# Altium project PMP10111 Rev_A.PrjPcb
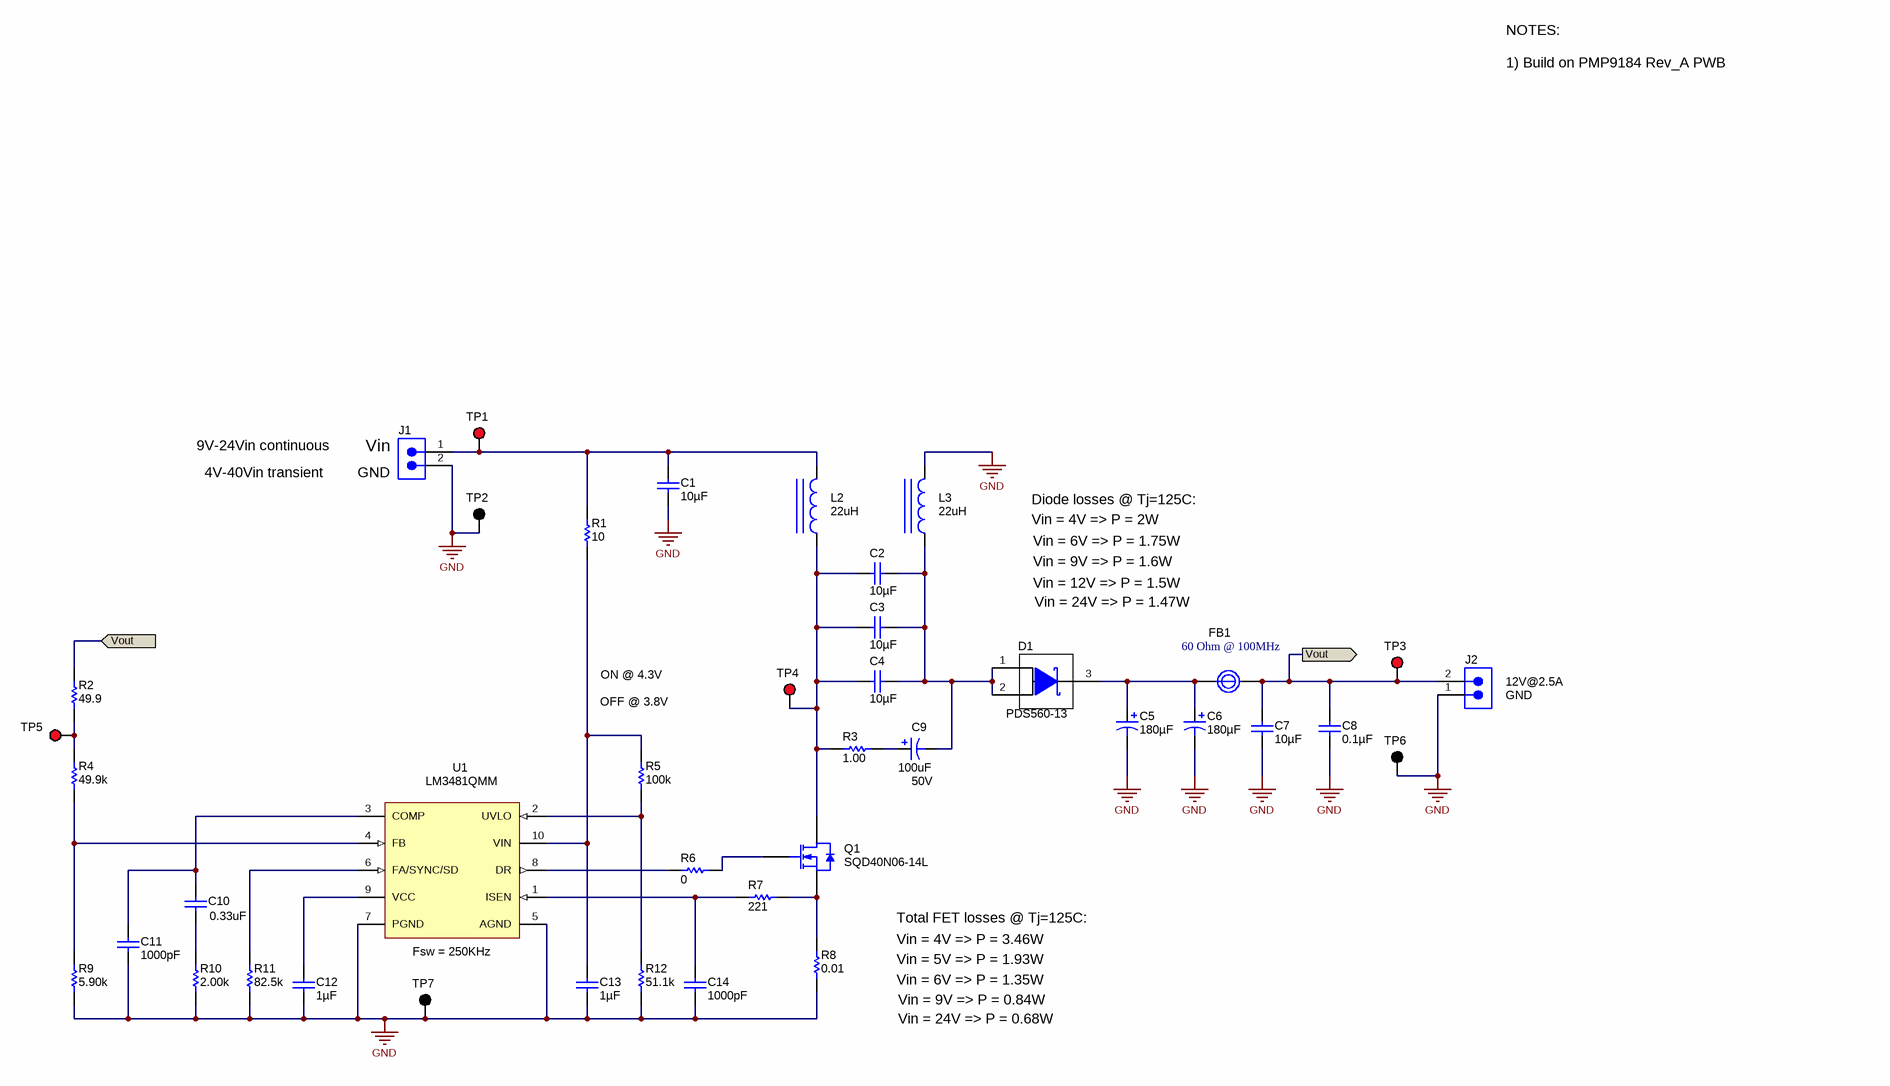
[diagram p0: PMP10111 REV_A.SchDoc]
CopyrightYear: 2014; PCB_Layout: R. Scibilia; PCB_Rev: A; PRJ_Customer: Public Release; PRJ_Engineer: R. Scibilia; PRJ_Number: PMP10111; PRJ_Title: LM3481 SEPIC converter; SCH_Rev: A; TechSupport: http://www.ti.com/support
1 sheet, 41 parts. Net scope: flat (ports and power ports of the same name join across sheets).

## Sheet PMP10111 REV_A.SchDoc: LM3481 SEPIC converter
size 431 x 279 mm; Date: Not shown in title block; ApprovedBy: Not shown in title block; CheckedBy: Not shown in title block; Author: Not shown in title block; CompanyName: Not shown in title block; DrawnBy: R. Scibilia; Engineer: Not shown in title block; Organization: Not shown in title block; Address1: Not shown in title block; Address2: Not shown in title block; Address3: Not shown in title block; Address4: Not shown in title block; DocumentNumber: 1; Revision: Use project parameter SCH_Rev; SheetNumber: 1; SheetTotal: 1; PageSetup: Record=PageOptions|CenterHorizontal=True|CenterVertical=True|PrintScale=1.00|XCorrection=1.00|YCorrection=1.00|PrintKind=0|BorderSize=5000000|LeftOffset=0|BottomOffset=0|Orientation=2|PaperLength=1000|PaperWidth=1000|Scale=100|PaperSource=15|PrintQuality=600|MediaType=1|DitherType=10|PaperKind=Letter|PrintScaleMode=1

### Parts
C1  ValueDisplayed: 10µF  [1210]  (hidden comment: GRM32ER71H106KA12L)
C2  ValueDisplayed: 10µF  [1210]  (hidden comment: GRM32ER71H106KA12L)
C3  ValueDisplayed: 10µF  [1210]  (hidden comment: GRM32ER71H106KA12L)
C4  ValueDisplayed: 10µF  [1210]  (hidden comment: GRM32ER71H106KA12L)
C5  ValueDisplayed: 180µF  [SM_RADIAL_10AMM]  (hidden comment: 25SVPF180M)
C6  ValueDisplayed: 180µF  [SM_RADIAL_10AMM]  (hidden comment: 25SVPF180M)
C7  ValueDisplayed: 10µF  [1210L]  (hidden comment: C3225X7R1E106M250AC)
C8  ValueDisplayed: 0.1µF  [0603L]  (hidden comment: C1608X7R1H104K)
C9  value 100uF  Value2: 50V  [SM_RADIAL_F]  (hidden comment: EEE-FK1H101P)
C10  value 0.33uF  [0603]  (hidden comment: GRM188R71C334KA01D)
C11  ValueDisplayed: 1000pF  [0603L]  (hidden comment: C1608X7R1H102K)
C12  ValueDisplayed: 1µF  [0603L]  (hidden comment: C1608X7R1E105K)
C13  ValueDisplayed: 1µF  [0603L]  (hidden comment: C1608X7R1E105K)
C14  ValueDisplayed: 1000pF  [0603L]  (hidden comment: C1608X7R1H102K)
D1  PDS560-13  [PowerDI5]
FB1  value 60 Ohm @ 100MHz  [BEAD-BLM41]  (hidden comment: BLM41PG600SH1)
J1  ED555/2DS  [TERM_BLK_ED555-2DS]  (value not drawn)
J2  ED555/2DS  [TERM_BLK_ED555-2DS]  (value not drawn)
L2  value 22uH  [IND_WE-HCI_2212]  (hidden comment: IHLP6767GZER220M5A)
L3  value 22uH  [WE-HCA2]  (hidden comment: IHLP4040DZER220M5A)
Q1  SQD40N06-14L  [DPAK]
R1  value 10  [0603L]  (hidden comment: CRCW060310R0JNEA)
R2  value 49.9  [0603L]  (hidden comment: CRCW060349R9FKEA)
R3  value 1.00  [1206L]  (hidden comment: CRCW12061R00FKEA)
R4  value 49.9k  [0603L]  (hidden comment: CRCW060349K9FKEA)
R5  value 100k  [0603L]  (hidden comment: CRCW0603100KFKEA)
R6  value 0  [0603L]  (hidden comment: CRCW06030000Z0EA)
R7  value 221  [0603L]  (hidden comment: CRCW0603221RFKEA)
R8  ValueDisplayed: 0.01  [2512]  (hidden comment: ERJ-M1WSF10MU)
R9  ValueDisplayed: 5.90k  [0603]  (hidden comment: CRCW06035K90FKEA)
R10  value 2.00k  [0603L]  (hidden comment: CRCW06032K00FKEA)
R11  ValueDisplayed: 82.5k  [0603]  (hidden comment: CRCW060382K5FKEA)
R12  ValueDisplayed: 51.1k  [0603]  (hidden comment: CRCW060351K1FKEA)
TP1  5000  [Keystone5000]  (value not drawn)
TP2  5001  [Keystone5001]  (value not drawn)
TP3  5000  [Keystone5000]  (value not drawn)
TP4  5000  [Keystone5000]  (value not drawn)
TP5  5000  [Keystone5000]  (value not drawn)
TP6  5001  [Keystone5001]  (value not drawn)
TP7  5001  [Keystone5001]  (value not drawn)
U1  value LM3481QMM  [MUB10A_L]  (hidden comment: LM3481MM)

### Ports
Vout

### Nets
GND: C1.2 C5.2(-) C6.2(-) C7.1 C8.2 C11.2 C12.2 C13.2 C14.2 J1.2 J2.1 L3.2 R8.1 R9.1 R10.1 R11.1 R12.1 TP2.1 TP6.1 TP7.1 U1.5(AGND) U1.7(PGND)
Vout: C7.2 C8.1 FB1.2 J2.2 R2.2 TP3.1 ; port Vout
NetC1_1: C1.1 J1.1 L2.2 R1.2 TP1.1
NetC2_1: C2.1 C3.1 C4.1 C9.2(-) D1.1(A) D1.2(A) L3.1
NetC2_2: C2.2 C3.2 C4.2 L2.1 Q1.4(D) R3.1 TP4.1
NetC5_1: C5.1(+) C6.1(+) D1.3(K) FB1.1
NetC9_1: C9.1(+) R3.2
NetC10_1: C10.1 C11.1 U1.3(COMP)
NetC10_2: C10.2 R10.2
NetC12_1: C12.1 U1.9(VCC)
NetC13_1: C13.1 R1.1 R5.2 U1.10(VIN)
NetC14_1: C14.1 R7.2 U1.1(ISEN)
NetQ1_1: Q1.1(G) R6.2
NetQ1_3: Q1.3(S) R7.1 R8.2
NetR2_1: R2.1 R4.2 TP5.1
NetR4_1: R4.1 R9.2 U1.4(FB)
NetR5_1: R5.1 R12.2 U1.2(UVLO)
NetR6_1: R6.1 U1.8(DR)
NetR11_2: R11.2 U1.6(FA/SYNC/SD)

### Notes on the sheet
- NOTES:
  1) Build on PMP9184 Rev_A PWB
- 4V-40Vin transient
- 9V-24Vin continuous
- (near J1) GND
- (near J1) Vin
- Vin = 4V => P = 2W
- Vin = 6V => P = 1.75W
- Diode losses @ Tj=125C:
- Vin = 9V => P = 1.6W
- Vin = 12V => P = 1.5W
- Vin = 24V => P = 1.47W
- ON @ 4.3V
- (near J2) 12V@2.5A
- OFF @ 3.8V
- (near J2) GND
- (near U1) Fsw = 250KHz
- Vin = 4V => P = 3.46W
- Total FET losses @ Tj=125C:
- Vin = 5V => P = 1.93W
- Vin = 6V => P = 1.35W
- Vin = 9V => P = 0.84W
- Vin = 24V => P = 0.68W

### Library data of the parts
C1-C4 = GRM32ER71H106KA12L: CAP, CERM, 10 µF, 50 V, +/- 10%, X7R, 1210; Manufacturer: MuRata; Polarized: N; CompType: Capacitor; Value: 10uF; U/M: EA; Cap_F: 0.00001; Tolerance_%: 10; Value1: Unknown; VDC_V: 50; Value2: 50V; TaMin_C: -55; TaMax_C: 125
C5 C6 = 25SVP22M: CAP, OS-CON, 180uF, 25V, +/-20%, 0.016 ohm, 10x10.3 SMD; Manufacturer: Sanyo; Polarized: Y; CompType: Capacitor; U/M: EA; Cap_F: 0.000022; Tolerance_%: 20; VDC_V: 25; ESR_Ohm: 0.05; IRMS_A: 2; TaMin_C: -55; TaMax_C: 105; Cap_Case: 10.3x10.3x7.9
C7 = C3225X7R1E106M: CAP, CERM, 10uF, 25V, +/-20%, X7R, 1210; Manufacturer: TDK; Polarized: N; CompType: Capacitor; U/M: EA; Cap_F: 0.00001; Tolerance_%: 20; ESR_Ohm: 0.0027; Value1: 0.0027 ohm; VDC_V: 25; IRMS_A: 3; TaMin_C: -55; TaMax_C: 125; Cap_Case: 1210
C8 = C1608X7R1H104K: CAP, CERM, 0.1uF, 50V, +/-10%, X7R, 0603; Manufacturer: TDK; Polarized: N; CompType: Capacitor; U/M: EA; Cap_F: 0.0000001; Tolerance_%: 10; ESR_Ohm: 0.017; Value1: 0.017 ohm; VDC_V: 50; TaMin_C: -55; TaMax_C: 125; Cap_Case: 0603
C9 = EEE-FK1E151P: CAP, AL, 100uF, 50V, +/-20%, 0.34 ohm, SMD; Manufacturer: Panasonic; Polarized: Y; CompType: Capacitor; U/M: EA; Cap_F: 0.00015; Tolerance_%: 20; VDC_V: 25; ESR_Ohm: 0.34; IRMS_A: 0.26A; TaMin_C: -55; TaMax_C: 105; Cap_Case: F
C10 = GRM188R71C334KA01D: CAP, CERM, 0.33 µF, 16 V, +/- 10%, X7R, 0603; Manufacturer: MuRata; Polarized: N; CompType: Capacitor; ValueDisplayed: 0.33µF; U/M: EA; Cap_F: 0.00000033; Tolerance_%: 10; Value1: Unknown; VDC_V: 16; Value2: 16V; TaMin_C: -55; TaMax_C: 125
C11 C14 = C1608X7R1H102K: CAP, CERM, 1000pF, 50V, +/-10%, X7R, 0603; Manufacturer: TDK; Polarized: N; CompType: Capacitor; U/M: EA; Cap_F: 0.000000001; Tolerance_%: 10; ESR_Ohm: 0.24; Value1: 0.24 ohm; VDC_V: 50; TaMin_C: -55; TaMax_C: 125; Cap_Case: 0603
C12 C13 = C1608X7R1C105K: CAP, CERM, 1uF, 25V, +/-10%, X7R, 0603; Manufacturer: TDK; Polarized: N; CompType: Capacitor; U/M: EA; Cap_F: 0.000001; Tolerance_%: 10; ESR_Ohm: 0.0057; Value1: 0.0057 ohm; VDC_V: 25; TaMin_C: -55; TaMax_C: 125; Cap_Case: 0603
D1 = PDS560-13: Diode, Schottky, 60 V, 5 A, PowerDI5; Manufacturer: Diodes Inc.; U/M: EA; Vf_V: 0.67; Value1: 5A; Value2: 0.67V; Io_A: 5; Vr_V: 60; TJmax_C: 150
FB1 = BEAD-BLM41_SERIES: Ferrite Chip, 60 Ohm @100MHz, 6A, Temp -55 to +125°C; Manufacturer: muRata; Area: 38,080
J1 J2 = ED555/2DS: Terminal Block, 6A, 3.5mm Pitch, 2-Pos, TH; Manufacturer: On-Shore Technology, Inc.; SymbolCreator: a0412235; CompType: Connector; U/M: EA
L2 = 74435581000: Inductor Automotive, Shielded Drum Core, 22uH, 11A, 0.021 ohm, SMD; Manufacturer: Vishay; ValueDisplayed: 22µH; Ind_H: 10.0E-6; Imax_A: 11; Irms: 11.7A @ 40C rise; Isat: 11A @ 20% inductance drop; DCR_ohm: 0.021; Material: Ferrite; U/M: EA
L3 = 7443551181: Inductor Automotive, Shielded, 22uH, 6.4A, 0.07 ohm, SMD; Manufacturer: Vishay; ValueDisplayed: 22µH; Ind_H: 18.0E-6; Imax_A: 7.5; Irms: 4.1A @ 40C rise; Isat: 6.4A @ 20% inductance drop; DCR_ohm: 0.022; Value1: 0.0247ohm; U/M: EA
Q1 = BUK6226-75C,118: MOSFET Automotive, N-CH, 60 V, 40 A, DPAK; Manufacturer: Vishay; Alternate Manufacturer: None; U/M: EA; ChType: N; VdsMax_V: 60; Value1: 0.017 ohm; Rdson45_ohm: 0.017; Value2: 34 nC; QgTyp_nC: 34; Vgs_V: 16; IdsMax_A: 33
R1 = CRCW060310R0JNEA: RES, 10 ohm, 1%, 0.1W, 0603; Manufacturer: Vishay-Dale; CompType: Resistor; Value_Code: 10R0; Tolerance_%: 5; Power_W: 0.1; VDC_V: 75; TempCo: 200 ppm/C; EIA_Code: E24; U/M: EA
R2 = CRCW060349R9FKEA: RES, 49.9 ohm, 1%, 0.1W, 0603; Manufacturer: Vishay-Dale; CompType: Resistor; Value_Code: 49R9; Tolerance_%: 1; Power_W: 0.1; VDC_V: 75; TempCo: 100 ppm/C; EIA_Code: E96; U/M: EA
R3 = CRCW12061R00FKEA: RES, 1.00 ohm, 1%, 0.25W, 1206; Manufacturer: Vishay-Dale; CompType: Resistor; Res_ohm: 1; Value_Code: 1R00; Power_W: 0.25; VDC_V: 200; TempCo: 100 ppm/C; EIA_Code: E96; U/M: EA
R4 = CRCW060349K9FKEA: RES, 49.9k ohm, 1%, 0.1W, 0603; Manufacturer: Vishay-Dale; CompType: Resistor; Res_ohm: 49900; Value_Code: 49k9; Tolerance_%: 1; Power_W: 0.1; VDC_V: 75; TempCo: 100 ppm/C; EIA_Code: E96; U/M: EA
R5 = CRCW0603100KFKEA: RES, 100k ohm, 1%, 0.1W, 0603; Manufacturer: Vishay-Dale; CompType: Resistor; Res_ohm: 100000; Tolerance_%: 1; Power_W: 0.1; VDC_V: 75; TempCo: 100 ppm/C; EIA_Code: E96; U/M: EA
R6 = CRCW06030000Z0EA: RES, 0 ohm, 5%, 0.1W, 0603; Manufacturer: Vishay-Dale; CompType: Resistor; Value_Code: 0000; Tolerance_%: 5; Power_W: 0.1; VDC_V: 75; TempCo: 200 ppm/C; EIA_Code: E24; U/M: EA
R7 = CRCW0603221RFKEA: RES, 221 ohm, 1%, 0.1W, 0603; Manufacturer: Vishay-Dale; CompType: Resistor; Value_Code: 221R; Tolerance_%: 1; Power_W: 0.1; VDC_V: 75; TempCo: 100 ppm/C; EIA_Code: E96; U/M: EA
R8 = ERJ-M1WSF10MU: RES, 0.01, 1%, 1 W, 2512; Manufacturer: Panasonic; CompType: Resistor; Value: 0.01; Value_Code: R010; Tolerance_%: 1; Value2: 1W; TempCo: 100 ppm/C; EIA_Code: E96; U/M: EA
R9 = CRCW06035K90FKEA: RES, 5.90 k, 1%, 0.1 W, 0603; Manufacturer: Vishay-Dale; CompType: Resistor; Value: 5.90k; Res_ohm: 5900; Value_Code: 5k90; Tolerance_%: 1; Power_W: 0.1; Value2: 0.1W; VDC_V: 75; TempCo: 100 ppm/C; EIA_Code: E96; U/M: EA
R10 = CRCW06032K00FKEA: RES, 2.00k ohm, 1%, 0.1W, 0603; Manufacturer: Vishay-Dale; CompType: Resistor; Res_ohm: 2000; Value_Code: 2k00; Tolerance_%: 1; Power_W: 0.1; VDC_V: 75; TempCo: 100 ppm/C; EIA_Code: E96; U/M: EA
R11 = CRCW060382K5FKEA: RES, 82.5 k, 1%, 0.1 W, 0603; Manufacturer: Vishay-Dale; CompType: Resistor; Value: 82.5k; Res_ohm: 82500; Value_Code: 82k5; Tolerance_%: 1; Power_W: 0.1; Value2: 0.1W; VDC_V: 75; TempCo: 100 ppm/C; EIA_Code: E96; U/M: EA
R12 = CRCW060351K1FKEA: RES, 51.1 k, 1%, 0.1 W, 0603; Manufacturer: Vishay-Dale; CompType: Resistor; Value: 51.1k; Res_ohm: 51100; Value_Code: 51k1; Tolerance_%: 1; Power_W: 0.1; Value2: 0.1W; VDC_V: 75; TempCo: 100 ppm/C; EIA_Code: E96; U/M: EA
TP1 TP3-TP5 = 5000: Test Point, TH, Miniature, Red; Manufacturer: Keystone; CompType: Test Point Loop; U/M: EA
TP2 TP6 TP7 = 5001: Test Point, TH, Miniature, Black; Manufacturer: Keystone; CompType: Test Point Loop; U/M: EA
U1 = LM3481MM: High Efficiency Automotive Low-Side N-Channel Controller for Switching Regulators, 10-pin MSOP; Manufacturer: Texas Instruments; PackageTopMarking: ZXTT*SJPB; PowerWise: N; CompType: MiscPower

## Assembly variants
001: all parts fitted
